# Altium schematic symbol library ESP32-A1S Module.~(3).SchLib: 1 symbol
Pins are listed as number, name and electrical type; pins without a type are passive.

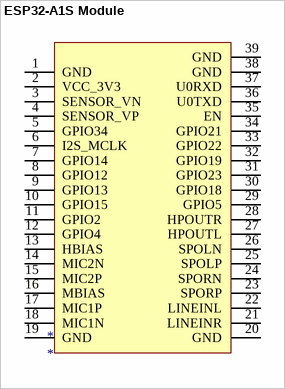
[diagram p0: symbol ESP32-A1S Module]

## ESP32-A1S Module
designator *
pins: 1 GND, 2 VCC_3V3, 3 SENSOR_VN, 4 SENSOR_VP, 5 GPIO34, 6 I2S_MCLK, 7 GPIO14, 8 GPIO12, 9 GPIO13, 10 GPIO15, 11 GPIO2, 12 GPIO4, 13 HBIAS, 14 MIC2N, 15 MIC2P, 16 MBIAS, 17 MIC1P, 18 MIC1N, 19 GND, 20 GND, 21 LINEINR, 22 LINEINL, 23 SPORP, 24 SPORN, 25 SPOLP, 26 SPOLN, 27 HPOUTL, 28 HPOUTR, 29 GPIO5, 30 GPIO18, 31 GPIO23, 32 GPIO19, 33 GPIO22, 34 GPIO21, 35 EN, 36 U0TXD, 37 U0RXD, 38 GND, 39 GND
